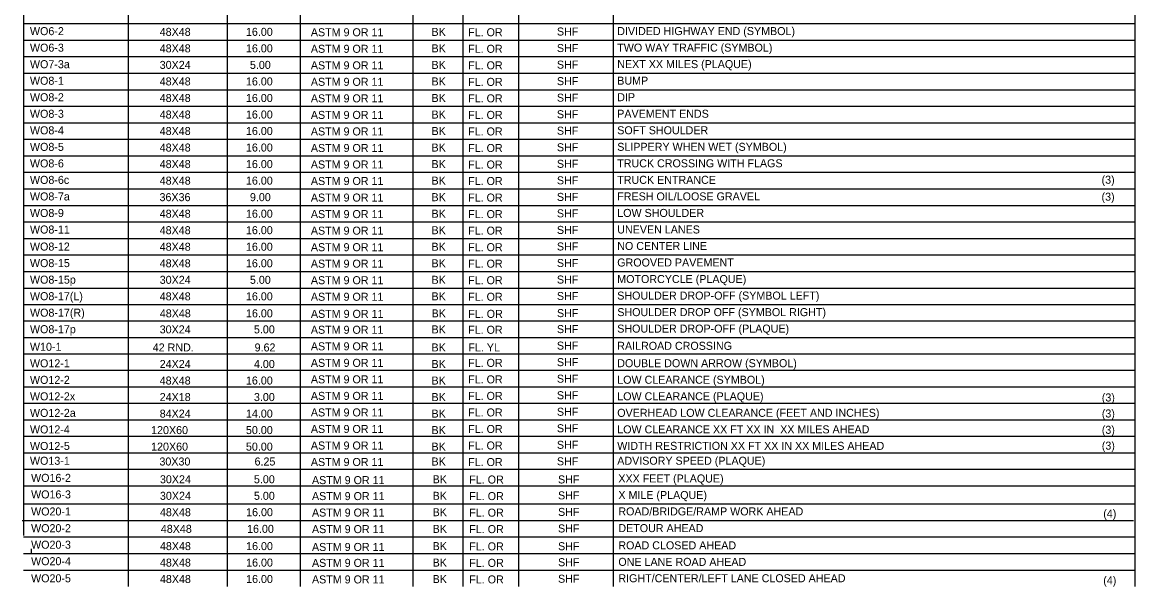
# Model space of a CAD drawing. Extents: x -439.1 to -408.3, y -458.1 to -437.7.
# Drawn here: x -439.13 to -419.21, y -458.05 to -447.95 of the extents above; entities that cross this region are included whole.
import ezdxf

# ---------------------------------------------------------------- set-up
doc = ezdxf.new("R2010")
doc.units = 0
for name, color, linetype in [('Common-Notes', 7, 'Continuous'), ('Level 4', 7, 'Continuous'), ('Level 45', 7, 'Continuous')]:
    doc.layers.add(name, color=color, linetype=linetype)

msp = doc.modelspace()

# ---------------------------------------------------------------- linework, layer by layer
at = {"layer": 'Common-Notes'}
msp.add_line((-438.971, -457.373), (-438.971, -457.458), dxfattribs=at)
at = {"layer": 'Level 4'}
for p, q in [((-439.109, -437.676), (-439.109, -457.138)), ((-419.212, -437.676), (-419.212, -458.051)), ((-437.233, -438.806), (-437.233, -458.051)), ((-435.462, -438.806), (-435.462, -458.051)), ((-434.152, -438.806), (-434.152, -458.051)), ((-432.136, -438.806), (-432.136, -458.051)), ((-431.24, -438.806), (-431.24, -458.051)), ((-430.244, -438.806), (-430.244, -458.051)), ((-428.547, -438.806), (-428.547, -458.051)), ((-439.109, -447.976), (-419.212, -447.976)), ((-439.109, -448.272), (-419.212, -448.272)), ((-439.109, -448.568), (-419.212, -448.568)), ((-439.109, -448.864), (-419.212, -448.864)), ((-439.109, -449.159), (-419.212, -449.159)), ((-439.109, -449.455), (-419.212, -449.455)), ((-439.109, -449.751), (-419.212, -449.751)), ((-439.109, -450.047), (-419.212, -450.047)), ((-439.109, -450.343), (-419.212, -450.343)), ((-439.109, -450.638), (-419.212, -450.638)), ((-439.109, -450.934), (-419.212, -450.934)), ((-439.109, -451.23), (-419.212, -451.23)), ((-439.109, -451.526), (-419.212, -451.526)), ((-439.109, -451.822), (-419.212, -451.822)), ((-439.109, -452.117), (-419.212, -452.117)), ((-439.109, -452.413), (-419.212, -452.413)), ((-439.109, -452.709), (-419.212, -452.709)), ((-439.109, -453.005), (-419.212, -453.005)), ((-439.109, -453.298), (-419.212, -453.298)), ((-439.109, -453.591), (-419.212, -453.591)), ((-439.109, -453.885), (-419.212, -453.885)), ((-439.109, -454.178), (-419.212, -454.178)), ((-439.109, -454.474), (-419.212, -454.474)), ((-439.109, -454.769), (-419.212, -454.769)), ((-439.109, -455.065), (-419.212, -455.065)), ((-439.109, -455.361), (-419.212, -455.361)), ((-439.109, -455.656), (-419.212, -455.656)), ((-439.109, -455.952), (-419.212, -455.952)), ((-439.109, -456.248), (-419.212, -456.248)), ((-439.109, -456.571), (-419.212, -456.571)), ((-439.129, -456.867), (-419.232, -456.867)), ((-439.109, -457.163), (-419.212, -457.163)), ((-439.109, -457.458), (-419.212, -457.458)), ((-439.109, -457.754), (-419.212, -457.754))]:
    msp.add_line(p, q, dxfattribs=at)

# ---------------------------------------------------------------- texts
for s, height, p in [('WO6-2', 0.1433, (-438.991, -448.183)), ('ASTM 9 OR 11', 0.14328, (-433.962, -448.203)), ('BK', 0.1433, (-431.802, -448.196)), ('FL. OR', 0.1433, (-431.146, -448.203)), ('SHF', 0.1433, (-429.557, -448.19)), ('DIVIDED HIGHWAY END (SYMBOL)', 0.14328, (-428.477, -448.182)), ('TWO WAY TRAFFIC (SYMBOL)', 0.14328, (-428.477, -448.478)), ('WO6-3', 0.1433, (-438.991, -448.479)), ('ASTM 9 OR 11', 0.14328, (-433.962, -448.499)), ('BK', 0.1433, (-431.802, -448.491)), ('FL. OR', 0.1433, (-431.146, -448.499)), ('SHF', 0.1433, (-429.557, -448.486)), ('WO7-3a', 0.1433, (-438.991, -448.775)), ('ASTM 9 OR 11', 0.14328, (-433.962, -448.795)), ('BK', 0.1433, (-431.802, -448.787)), ('FL. OR', 0.1433, (-431.146, -448.795)), ('SHF', 0.1433, (-429.557, -448.782)), ('NEXT XX MILES (PLAQUE)', 0.14328, (-428.477, -448.773)), ('WO8-1 ', 0.1433, (-438.991, -449.071)), ('BUMP', 0.1433, (-428.477, -449.069)), ('ASTM 9 OR 11', 0.14328, (-433.962, -449.09)), ('BK', 0.1433, (-431.802, -449.083)), ('FL. OR', 0.1433, (-431.146, -449.091)), ('SHF', 0.1433, (-429.557, -449.078)), ('WO8-2 ', 0.1433, (-438.991, -449.366)), ('ASTM 9 OR 11', 0.14328, (-433.962, -449.386)), ('BK', 0.1433, (-431.802, -449.379)), ('FL. OR', 0.1433, (-431.146, -449.386)), ('SHF', 0.1433, (-429.557, -449.374)), ('DIP', 0.1433, (-428.477, -449.365)), ('WO8-3', 0.1433, (-438.991, -449.662)), ('PAVEMENT ENDS', 0.14328, (-428.477, -449.661)), ('ASTM 9 OR 11', 0.14328, (-433.962, -449.682)), ('BK', 0.1433, (-431.802, -449.675)), ('FL. OR', 0.1433, (-431.146, -449.682)), ('SHF', 0.1433, (-429.557, -449.67)), ('WO8-4 ', 0.1433, (-438.991, -449.958)), ('ASTM 9 OR 11', 0.14328, (-433.962, -449.978)), ('BK', 0.1433, (-431.802, -449.97)), ('FL. OR', 0.1433, (-431.146, -449.978)), ('SHF', 0.1433, (-429.557, -449.965)), ('SOFT SHOULDER', 0.14328, (-428.477, -449.957)), ('WO8-5 ', 0.1433, (-438.991, -450.254)), ('SHF', 0.1433, (-429.557, -450.261)), ('SLIPPERY WHEN WET (SYMBOL) ', 0.14328, (-428.477, -450.253)), ('ASTM 9 OR 11', 0.14328, (-433.962, -450.274)), ('BK', 0.1433, (-431.802, -450.266)), ('FL. OR', 0.1433, (-431.146, -450.274)), ('WO8-6 ', 0.1433, (-438.991, -450.55)), ('ASTM 9 OR 11', 0.14328, (-433.962, -450.569)), ('BK', 0.1433, (-431.802, -450.562)), ('FL. OR', 0.1433, (-431.146, -450.57)), ('SHF', 0.1433, (-429.557, -450.557)), ('TRUCK CROSSING WITH FLAGS', 0.14328, (-428.477, -450.548)), ('WO8-6c', 0.1433, (-438.991, -450.845)), ('BK', 0.1433, (-431.802, -450.858)), ('SHF', 0.1433, (-429.557, -450.853)), ('TRUCK ENTRANCE ', 0.14328, (-428.477, -450.844)), ('(3)', 0.1433, (-419.806, -450.842)), ('ASTM 9 OR 11', 0.14328, (-433.962, -450.865)), ('FL. OR', 0.1433, (-431.146, -450.865)), ('WO8-7a ', 0.1433, (-438.991, -451.141)), ('ASTM 9 OR 11', 0.14328, (-433.962, -451.161)), ('BK', 0.1433, (-431.802, -451.154)), ('FL. OR', 0.1433, (-431.146, -451.161)), ('SHF', 0.1433, (-429.557, -451.149)), ('FRESH OIL/LOOSE GRAVEL', 0.14328, (-428.477, -451.14)), ('(3)', 0.1433, (-419.807, -451.146)), ('WO8-9', 0.1433, (-438.991, -451.437)), ('ASTM 9 OR 11', 0.14328, (-433.962, -451.457)), ('BK', 0.1433, (-431.802, -451.45)), ('FL. OR', 0.1433, (-431.146, -451.457)), ('SHF', 0.1433, (-429.557, -451.444)), ('LOW SHOULDER', 0.14328, (-428.477, -451.436)), ('WO8-11', 0.1433, (-438.991, -451.733)), ('ASTM 9 OR 11', 0.14328, (-433.962, -451.753)), ('BK', 0.1433, (-431.802, -451.745)), ('FL. OR', 0.1433, (-431.146, -451.753)), ('SHF', 0.1433, (-429.557, -451.74)), ('UNEVEN LANES', 0.14328, (-428.477, -451.732)), ('WO8-12', 0.1433, (-438.991, -452.038)), ('ASTM 9 OR 11', 0.14328, (-433.962, -452.049)), ('BK', 0.1433, (-431.802, -452.041)), ('FL. OR', 0.1433, (-431.146, -452.049)), ('SHF', 0.1433, (-429.557, -452.036)), ('NO CENTER LINE', 0.14328, (-428.477, -452.027)), ('WO8-15', 0.1433, (-438.991, -452.334)), ('ASTM 9 OR 11', 0.14328, (-433.962, -452.344)), ('BK', 0.1433, (-431.802, -452.337)), ('FL. OR', 0.1433, (-431.146, -452.344)), ('SHF', 0.1433, (-429.557, -452.332)), ('GROOVED PAVEMENT', 0.14328, (-428.477, -452.323)), ('WO8-15p', 0.1433, (-438.991, -452.63)), ('ASTM 9 OR 11', 0.14328, (-433.962, -452.64)), ('BK', 0.1433, (-431.802, -452.633)), ('FL. OR', 0.1433, (-431.146, -452.64)), ('SHF', 0.1433, (-429.557, -452.628)), ('MOTORCYCLE (PLAQUE)', 0.14328, (-428.477, -452.619)), ('WO8-17(L)', 0.1433, (-438.991, -452.926)), ('ASTM 9 OR 11', 0.14328, (-433.962, -452.936)), ('BK', 0.1433, (-431.802, -452.929)), ('FL. OR', 0.1433, (-431.146, -452.936)), ('SHF', 0.1433, (-429.557, -452.923)), ('SHOULDER DROP-OFF (SYMBOL LEFT)', 0.14328, (-428.477, -452.915)), ('WO8-17(R)', 0.1433, (-438.99, -453.221)), ('ASTM 9 OR 11', 0.14328, (-433.961, -453.242)), ('BK', 0.1433, (-431.8, -453.233)), ('FL. OR', 0.1433, (-431.144, -453.242)), ('SHF', 0.1433, (-429.556, -453.229)), ('SHOULDER DROP OFF (SYMBOL RIGHT)', 0.14328, (-428.476, -453.211)), ('WO8-17p', 0.1433, (-438.991, -453.517)), ('ASTM 9 OR 11', 0.14328, (-433.962, -453.527)), ('BK', 0.1433, (-431.802, -453.52)), ('FL. OR', 0.1433, (-431.146, -453.527)), ('SHF', 0.1433, (-429.557, -453.515)), ('SHOULDER DROP-OFF (PLAQUE)', 0.14328, (-428.477, -453.506)), ('W10-1', 0.1433, (-438.991, -453.831)), ('ASTM 9 OR 11', 0.14328, (-433.962, -453.823)), ('BK', 0.1433, (-431.802, -453.843)), ('FL. YL', 0.1433, (-431.142, -453.843)), ('SHF', 0.1433, (-429.557, -453.81)), ('RAILROAD CROSSING', 0.14328, (-428.477, -453.814)), ('WO12-1', 0.1433, (-438.991, -454.127)), ('ASTM 9 OR 11', 0.14328, (-433.962, -454.119)), ('BK', 0.1433, (-431.802, -454.139)), ('FL. OR', 0.1433, (-431.146, -454.119)), ('SHF', 0.1433, (-429.557, -454.106)), ('DOUBLE DOWN ARROW (SYMBOL)', 0.14328, (-428.477, -454.125)), ('WO12-2 ', 0.1433, (-438.991, -454.423)), ('ASTM 9 OR 11', 0.14328, (-433.962, -454.414)), ('BK', 0.1433, (-431.802, -454.435)), ('FL. OR', 0.1433, (-431.146, -454.415)), ('SHF', 0.1433, (-429.557, -454.402)), ('LOW CLEARANCE (SYMBOL)', 0.14328, (-428.477, -454.421)), ('WO12-2x', 0.1433, (-438.991, -454.718)), ('ASTM 9 OR 11', 0.14328, (-433.962, -454.71)), ('BK', 0.1433, (-431.802, -454.731)), ('FL. OR', 0.1433, (-431.146, -454.71)), ('SHF', 0.1433, (-429.557, -454.698)), ('LOW CLEARANCE (PLAQUE)', 0.14328, (-428.477, -454.717)), ('(3)', 0.1433, (-419.802, -454.738)), ('WO12-2a', 0.1433, (-438.991, -455.014)), ('ASTM 9 OR 11', 0.14328, (-433.962, -455.006)), ('BK', 0.1433, (-431.802, -455.027)), ('FL. OR', 0.1433, (-431.146, -455.006)), ('SHF', 0.1433, (-429.557, -454.994)), ('OVERHEAD LOW CLEARANCE (FEET AND INCHES)', 0.14328, (-428.477, -455.013)), ('(3)', 0.1433, (-419.802, -455.025)), ('WO12-4', 0.1433, (-438.991, -455.31)), ('ASTM 9 OR 11', 0.14328, (-433.962, -455.302)), ('BK', 0.1433, (-431.802, -455.322)), ('FL. OR', 0.1433, (-431.146, -455.302)), ('SHF', 0.1433, (-429.557, -455.289)), ('LOW CLEARANCE XX FT XX IN  XX MILES AHEAD', 0.14328, (-428.477, -455.309)), ('(3)', 0.1433, (-419.802, -455.317)), ('WO12-5', 0.1433, (-438.991, -455.606)), ('ASTM 9 OR 11', 0.14328, (-433.962, -455.598)), ('BK', 0.1433, (-431.802, -455.618)), ('FL. OR', 0.1433, (-431.146, -455.598)), ('SHF', 0.1433, (-429.557, -455.585)), ('WIDTH RESTRICTION XX FT XX IN XX MILES AHEAD', 0.14328, (-428.477, -455.604)), ('(3)', 0.1433, (-419.802, -455.6)), ('WO13-1 ', 0.1433, (-438.991, -455.871)), ('ASTM 9 OR 11', 0.14328, (-433.962, -455.893)), ('BK', 0.1433, (-431.802, -455.884)), ('FL. OR', 0.1433, (-431.146, -455.894)), ('SHF', 0.1433, (-429.557, -455.881)), ('ADVISORY SPEED (PLAQUE)', 0.14328, (-428.477, -455.87)), ('WO16-2', 0.1433, (-438.971, -456.177)), ('ASTM 9 OR 11', 0.14328, (-433.942, -456.217)), ('BK', 0.1433, (-431.782, -456.202)), ('FL. OR', 0.1433, (-431.126, -456.207)), ('SHF', 0.1433, (-429.537, -456.205)), ('XXX FEET (PLAQUE)', 0.14328, (-428.457, -456.188)), ('WO16-3', 0.1433, (-438.971, -456.473)), ('ASTM 9 OR 11', 0.14328, (-433.942, -456.503)), ('BK', 0.1433, (-431.782, -456.498)), ('FL. OR', 0.1433, (-431.126, -456.503)), ('SHF', 0.1433, (-429.537, -456.49)), ('X MILE (PLAQUE)', 0.14328, (-428.457, -456.484)), ('WO20-1', 0.1433, (-438.971, -456.778)), ('ASTM 9 OR 11', 0.14328, (-433.942, -456.798)), ('BK', 0.1433, (-431.782, -456.791)), ('FL. OR', 0.1433, (-431.126, -456.799)), ('SHF', 0.1433, (-429.537, -456.786)), ('ROAD/BRIDGE/RAMP WORK AHEAD ', 0.14328, (-428.457, -456.777)), ('(4)', 0.1433, (-419.776, -456.815)), ('WO20-2', 0.1433, (-438.971, -457.077)), ('ASTM 9 OR 11', 0.14328, (-433.942, -457.094)), ('BK', 0.1433, (-431.782, -457.089)), ('FL. OR', 0.1433, (-431.126, -457.094)), ('SHF', 0.1433, (-429.537, -457.082)), ('DETOUR AHEAD', 0.14328, (-428.457, -457.076)), ('WO20-3', 0.1433, (-438.971, -457.373)), ('ASTM 9 OR 11', 0.14328, (-433.942, -457.413)), ('BK', 0.1433, (-431.782, -457.398)), ('FL. OR', 0.1433, (-431.126, -457.403)), ('SHF', 0.1433, (-429.537, -457.4)), ('ROAD CLOSED AHEAD', 0.14328, (-428.457, -457.384)), ('WO20-4', 0.1433, (-438.971, -457.668)), ('ASTM 9 OR 11', 0.14328, (-433.942, -457.698)), ('BK', 0.1433, (-431.782, -457.693)), ('FL. OR', 0.1433, (-431.126, -457.698)), ('SHF', 0.1433, (-429.537, -457.686)), ('ONE LANE ROAD AHEAD', 0.14328, (-428.457, -457.68)), ('WO20-5', 0.1433, (-438.971, -457.974)), ('ASTM 9 OR 11', 0.14328, (-433.942, -457.994)), ('BK', 0.1433, (-431.782, -457.987)), ('FL. OR', 0.1433, (-431.126, -457.994)), ('SHF', 0.1433, (-429.537, -457.982)), ('RIGHT/CENTER/LEFT LANE CLOSED AHEAD ', 0.14328, (-428.457, -457.973)), ('(4)', 0.1433, (-419.776, -458.01))]:
    msp.add_text(s, height=height, dxfattribs=at).set_placement(p)
at = {"layer": 'Level 45'}
for s, p in [('48X48', (-436.668, -448.196)), ('16.00', (-435.124, -448.196)), ('48X48', (-436.668, -448.491)), ('16.00', (-435.124, -448.491)), ('30X24', (-436.668, -448.787)), ('5.00', (-435.053, -448.787)), ('48X48', (-436.668, -449.083)), ('16.00', (-435.124, -449.083)), ('48X48', (-436.668, -449.379)), ('16.00', (-435.124, -449.379)), ('48X48', (-436.668, -449.675)), ('16.00', (-435.124, -449.675)), ('48X48', (-436.668, -449.97)), ('16.00', (-435.124, -449.97)), ('48X48', (-436.668, -450.266)), ('16.00', (-435.124, -450.266)), ('48X48', (-436.668, -450.562)), ('16.00', (-435.124, -450.562)), ('48X48', (-436.668, -450.858)), ('16.00', (-435.124, -450.858)), ('36X36', (-436.671, -451.154)), ('9.00', (-435.053, -451.154)), ('48X48', (-436.668, -451.45)), ('16.00', (-435.124, -451.45)), ('48X48', (-436.668, -451.745)), ('16.00', (-435.124, -451.745)), ('48X48', (-436.668, -452.041)), ('16.00', (-435.124, -452.041)), ('48X48', (-436.668, -452.337)), ('16.00', (-435.124, -452.337)), ('30X24', (-436.668, -452.633)), ('5.00', (-435.053, -452.633)), ('48X48', (-436.668, -452.929)), ('16.00', (-435.124, -452.929)), ('48X48', (-436.666, -453.233)), ('16.00', (-435.123, -453.233)), ('30X24', (-436.668, -453.52)), ('5.00', (-434.981, -453.52)), ('42 RND.', (-436.793, -453.843)), ('9.62', (-434.969, -453.843)), ('24X24', (-436.668, -454.139)), ('4.00', (-434.981, -454.139)), ('48X48', (-436.668, -454.435)), ('16.00', (-435.124, -454.435)), ('24X18', (-436.668, -454.731)), ('3.00', (-434.981, -454.731)), ('84X24', (-436.668, -455.027)), ('14.00', (-435.124, -455.027)), ('120X60', (-436.822, -455.322)), ('50.00', (-435.124, -455.322)), ('120X60', (-436.822, -455.618)), ('50.00', (-435.124, -455.618)), ('30X30', (-436.673, -455.884)), ('6.25', (-434.97, -455.884)), ('30X24', (-436.664, -456.202)), ('5.00', (-434.981, -456.202)), ('30X24', (-436.664, -456.498)), ('5.00', (-434.981, -456.498)), ('48X48', (-436.664, -456.791)), ('16.00', (-435.121, -456.791)), ('48X48', (-436.648, -457.089)), ('16.00', (-435.104, -457.089)), ('48X48', (-436.664, -457.398)), ('16.00', (-435.121, -457.398)), ('48X48', (-436.664, -457.693)), ('16.00', (-435.121, -457.693)), ('48X48', (-436.664, -457.987)), ('16.00', (-435.121, -457.987))]:
    msp.add_text(s, height=0.1433, dxfattribs=at).set_placement(p)

doc.saveas('drawing.dxf')
